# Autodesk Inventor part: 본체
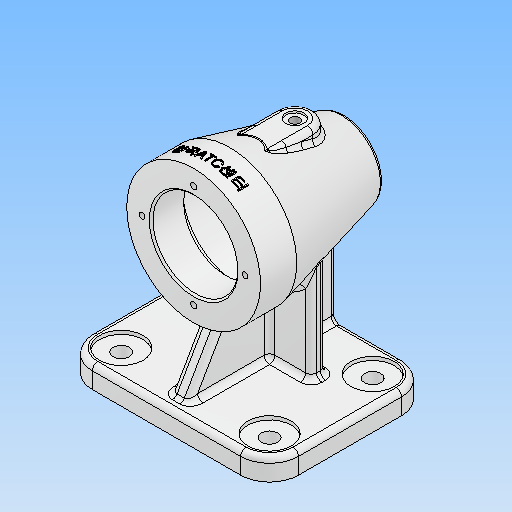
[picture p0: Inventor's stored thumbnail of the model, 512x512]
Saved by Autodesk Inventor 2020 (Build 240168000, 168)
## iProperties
Created: 2024-12
Part Number: 본체
Material: 알루미늄 6061
Document SubType Name: Modeling
Designer: 1강의실14
Density: 2.7 g/cm^3
Appearance: 알루미늄 - 평지
Mass: 746.273 g
Surface Area: 672.063 cm^2
Volume: 276.397 cm^3
Author: 1강의실14
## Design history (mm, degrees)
sketch "스케치2"
  geometry: C1 r 37 at (0, 0); 1 further point
  constraints: 1 centre point, 1 coincident
  dimensions: "d15" = 74 diameter of C1
extrude "돌출1" new body sketch "스케치2" distance "d16" = 20; taper "d17" = 0 deg
sketch "스케치3"
  geometry: L1 (-37, -20)-(37, -20) reference; L2 (0, -20)-(0, -84); L3 (0, -84)-(21, -84); L4 (21, -84)-(37, -20); L5 (37, -20)-(0, -20); 1 further point
  constraints: 8 end point, 1 collinear, 1 horizontal, 1 midpoint
  dimensions: "d19" = 64 distance of L2.start L2.end; "d22" = 21 distance of L2.end L3.end; "d24" = 42 diameter of L3.end L2
revolve "회전1" sketch "스케치3" stored, may be unused: angle "d25" = 90 deg
sketch "스케치4"
  geometry: L1 (0, 0)-(0, -76); L2 (-21, -84)-(21, -84) reference; L3 (37, 0)-(-37, 0) reference; L4 (23.5, 0)-(23.5, -18); L5 (23.5, -18)-(25.596, -18); L6 (30.447, -24.213)-(21.318, -60.728); L7 (18.408, -63)-(18.5, -63); L8 (17.5, -64)-(17.5, -72.7); L9 (17.2, -73)-(15.5, -73); L10 (15.5, -73)-(15.5, -73); L11 (12.5, -76)-(0, -76); L12 (37, -20)-(21, -84) reference; L13 (18.5, -63)-(17.5, -64); L14 (23.5, 0)-(0, 0); A1 r 0.3 centre (17.2, -72.7) between (17.2, -73) and (17.5, -72.7); A2 r 5 centre (25.596, -23) between (30.447, -24.213) and (25.596, -18); A3 r 3 centre (18.408, -60) between (18.408, -63) and (21.318, -60.728); A4 r 3 centre (12.5, -73) between (12.5, -76) and (15.5, -73); 3 further points
  constraints: 22 end point, 8 point on circle, 8 tangent, 6 perpendicular, 5 point on line, 4 centre point, 2 parallel, 1 collinear
  dimensions: "d26" = 31 diameter of L10 L1; "d27" = 35 diameter of L8 L1; "d28" = 47 diameter of L4 L1; "d30" = 64 diameter of point (32, -18) L1; "d32" = 18 distance between parallel lines of L5 L3; "d33" = 45 distance between parallel lines of L7 L5; "d34" = 10 distance between parallel lines of L9 L7; "d35" = 3 distance between parallel lines of L11 L9; "d36" = 0.3 radius of A1 (derived); "d37" = 5 radius of A2 (derived); "d38" = 3 radius of A3 (derived); "d39" = 1 distance of L7.end point (17.5, -63); "d40" = 1 distance of L8.start point (17.5, -63) (= d39); "d41" = 3 radius of A4
revolve "회전2" stored, may be unused: angle "d42" = 360 deg
node "작업 평면1"
sketch "스케치5"
  geometry: L1 (57, -74)-(-57, -74); L2 (-57, -74)-(-57, 15); L3 (-57, 15)-(57, 15); L4 (57, 15)-(57, -74); L5 (37, 0)-(-37, 0) reference; 1 further point
  constraints: 8 end point, 2 parallel, 1 horizontal, 1 perpendicular
  dimensions: "d45" = 114 distance between parallel lines of L2 L4; "d46" = 89 distance between parallel lines of L3 L1; "d47" = 57 distance from line of L4 point (0, 0); "d50" = 15 distance between parallel lines of L3 L5
extrude "돌출2" join sketch "스케치5" distance "d48" = 12; taper "d49" = 0 deg
sketch "스케치6"
  geometry: L1 (-28, 45)-(28, 45); L2 (28, 45)-(28, 37); L3 (28, 37)-(-28, 37); L4 (-28, 37)-(-28, 45); L5 (57, 74)-(-57, 74) reference; 1 further point
  constraints: 8 end point, 2 parallel, 1 horizontal, 1 perpendicular
  dimensions: "d51" = 8 distance between parallel lines of L3 L1; "d52" = 56 distance between parallel lines of L2 L4; "d53" = 28 distance from line of L4 point (0, 0); "d54" = 29 distance between parallel lines of L1 L5
extrude "돌출3" join sketch "스케치6" stored distance "d55" = 12; taper "d56" = 0 deg
sketch "스케치7"
  geometry: L1 (-21, -84)-(21, -84) reference; L2 (-37, -20)-(37, -20) reference; L3 (-16.987, -37)-(-16.987, -37) reference; L4 (-12.711, -45)-(-12.711, -45) reference; L5 (-70, -74)-(-70, 15) reference; L6 (-37, -20)-(-21, -84) reference; L7 (-37, -11.053)-(-70, 8); L8 (-82, 15)-(-70, 15) reference; L9 (-37, -20)-(37, -20) reference; L10 (37, 0)-(-37, 0) reference; L11 (-37, 0)-(-37, -20) reference; 1 further point
  constraints: 2 end point, 2 point on line, 2 other
  dimensions: "d57" = 60 deg angle of L7 L5; "d58" = 7 distance from line of L8 L7.end
feature "리브1" sketch "스케치7" dims "d59" = 1, "d60" = 10, "d61" = 0, "d62" = 0, "d63" = 1, "d64" = 1
sketch "스케치8"
  geometry: L1 (-30.75, -45)-(-21, -84) reference; L2 (-82, -74)-(-70, -74) reference; L3 (-70, -74)-(-23.5, -74); 1 further point
  constraints: 2 end point, 1 collinear, 1 point on line
feature "리브2" sketch "스케치8" dims "d65" = 1, "d66" = 10, "d67" = 0, "d68" = 0, "d69" = 1, "d70" = 1
node "작업 평면3"
sketch "스케치10"
  geometry: L1 (0, -66)-(0, -9.888); L2 (10, -56)-(10, -19.888); L3 (-10, -19.888)-(-10, -56); L4 (37, 0)-(-37, 0) reference; L5 (-5, -11.249)-(-5, -20) reference; L6 (5, -20)-(-5, -20) reference; L7 (5, -20)-(5, -11.249) reference; L8 (37, 0)-(-37, 0) reference; A1 r 10 centre (0, -56) between (-10, -56) and (10, -56); A2 r 10 centre (0, -19.888) between (10, -19.888) and (-10, -19.888); 3 further points; 1 other entity
  constraints: 8 end point, 6 point on circle, 4 tangent, 2 centre point, 2 point on line, 1 midpoint, 1 parallel, 1 vertical, 1 other
  dimensions: "d77" = 20 diameter of A2; "d79" = 56 distance from line of L4 A1.centre; "d80" = 10 distance from line of L2 point (0, 0); "d81" = 56 distance of A1.centre point (0, 0)
  node "투영된 루프3"
sketch "스케치11"
  geometry: L1 (57, 74)-(-57, 74) reference; 5 further points
  constraints: 2 horizontal alignment, 2 vertical alignment
  dimensions: "d84" = 16 distance from line of point (41, 58) L1; "d85" = 57 distance of point (41, 1) point (41, 58); "d86" = 82 distance of point (-41, 58) point (41, 58); "d87" = 41 horizontal distance of point (41, 58) point (0, 0)
hole "구멍1" sketch "스케치11" at (-41, 58), (41, 58), (41, 1), (-41, 1) diameter "d88" = 9; stored, may be unused: countersink angle "d92" = 82 deg, drill point angle "d94" = 0 deg; dims "d89" = 6, "d90" = 24, "d91" = 2, "d93" = 12
extrude "돌출6" join sketch "스케치10" distance "d97" = 10; taper "d98" = 0 deg
revolve "회전3" stored, may be unused: angle "d99" = 90 deg
revolve "회전4" stored, may be unused: angle "d100" = 90 deg
sketch "스케치13" dims "d101" = 57
  geometry: 3 further points
  constraints: 2 vertical alignment, 1 coincident, 2 other
hole "구멍2" sketch "스케치13" at (0, 28.5) diameter "d102" = 3.242; stored, may be unused: countersink angle "d106" = 82 deg, drill point angle "d108" = 120 deg; dims "d103" = 8, "d104" = 24, "d105" = 2, "d107" = 10
node "작업 평면4"
sketch "스케치14"
  geometry: L1 (37, 0)-(-37, 0) reference; 3 further points
  constraints: 1 midpoint, 1 vertical alignment, 1 other
  dimensions: "d112" = 9 distance from line of point (0, -9) L1
feature "엠보싱1" sketch "스케치14" dims "d113" = 0.5, "d114" = 0
fillet "모깎기1" dims "d115" = 3
fillet "모깎기2" dims "d116" = 3
fillet "모깎기3" dims "d117" = 16
fillet "모깎기4" dims "d118" = 3
sketch "스케치15"
  geometry: A1 r 10 centre (0, 56) between (10, 56) and (-10, 56) reference; 2 further points
  constraints: 1 coincident
hole "구멍3" sketch "스케치15" at (0, 56) diameter "d119" = 5.1881; stored, may be unused: countersink angle "d123" = 82 deg, drill point angle "d125" = 120 deg; dims "d120" = 15, "d121" = 10, "d122" = 1, "d124" = 16
fillet "모깎기6" dims "d127" = 3
fillet "모깎기7" dims "d128" = 3
chamfer "모따기1" distance "d129" = 1; stored, may be unused: second distance "d130" = 2, angle "d131" = 45 deg
node "솔리드1"
pattern_circular "원형 패턴1" dims angle "d110" = 360 deg
node "투영된 루프1"
node "투영된 루프2"
feature "A9D066F2-1C7D-4E18-AEED-F7BC21143FA4" dims "d88" = 9, "d89" = 6, "d90" = 24, "d91" = 2, "d92" = 82 deg, "d93" = 12, "d94" = 0
other parameters: "d43" = -82, "d76" = -115
